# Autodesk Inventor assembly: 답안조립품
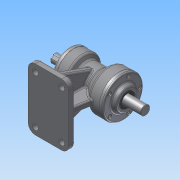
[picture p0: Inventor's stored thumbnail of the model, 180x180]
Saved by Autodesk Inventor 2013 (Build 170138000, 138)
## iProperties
Created: 2015-08
Part Number: 답안조립품
Document SubType Name: Assembly
Designer: Administrator
Author: Administrator
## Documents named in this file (10)
- C:\Users\Administrator\Desktop\450806V1023\답안조립품.iam
- C:\Users\Administrator\Desktop\450806V1023\M4x0.5.ipt
- C:\Users\Administrator\Desktop\450806V1023\뒤커버.ipt
- C:\Users\Administrator\Desktop\450806V1023\베어링 6203.ipt
- C:\Users\Administrator\Desktop\450806V1023\베어링 6205.ipt
- C:\Users\Administrator\Desktop\450806V1023\본체.ipt
- C:\Users\Administrator\Desktop\450806V1023\앞커버.ipt
- C:\Users\Administrator\Desktop\450806V1023\오일실 .ipt
- 오일실 .ipt
- C:\Users\Administrator\Desktop\450806V1023\축.ipt
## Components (10 placed, 1 different names)
1. M4x0.5:1
2. M4x0.5:3
3. M4x0.5:4
4. M4x0.5:5
5. M4x0.5:6
6. M4x0.5:2
7. M4x0.5:7
8. M4x0.5:8
9. M4x0.5:9
10. M4x0.5:10
